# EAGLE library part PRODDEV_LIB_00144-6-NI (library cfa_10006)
2X3 HDR, CONN HDR BRKWAY .100 VERT
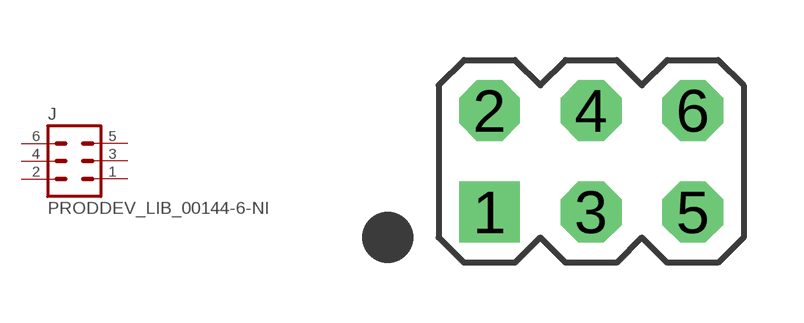
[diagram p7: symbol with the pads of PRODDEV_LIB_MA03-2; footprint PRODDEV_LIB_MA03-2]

Designator prefix J

## PRODDEV_LIB_00144-6-NI  [PRODDEV_LIB_MA03-2]
1  1  pas
2  2  pas
3  3  pas
4  4  pas
5  5  pas
6  6  pas

## Footprint PRODDEV_LIB_MA03-2 (pad centres in mm)
PIN HEADER
drill 1.016 square: 1 -2.54,-1.27
drill 1.016 octagon: 2 -2.54,1.27; 3 0,-1.27; 4 0,1.27; 5 2.54,-1.27; 6 2.54,1.27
